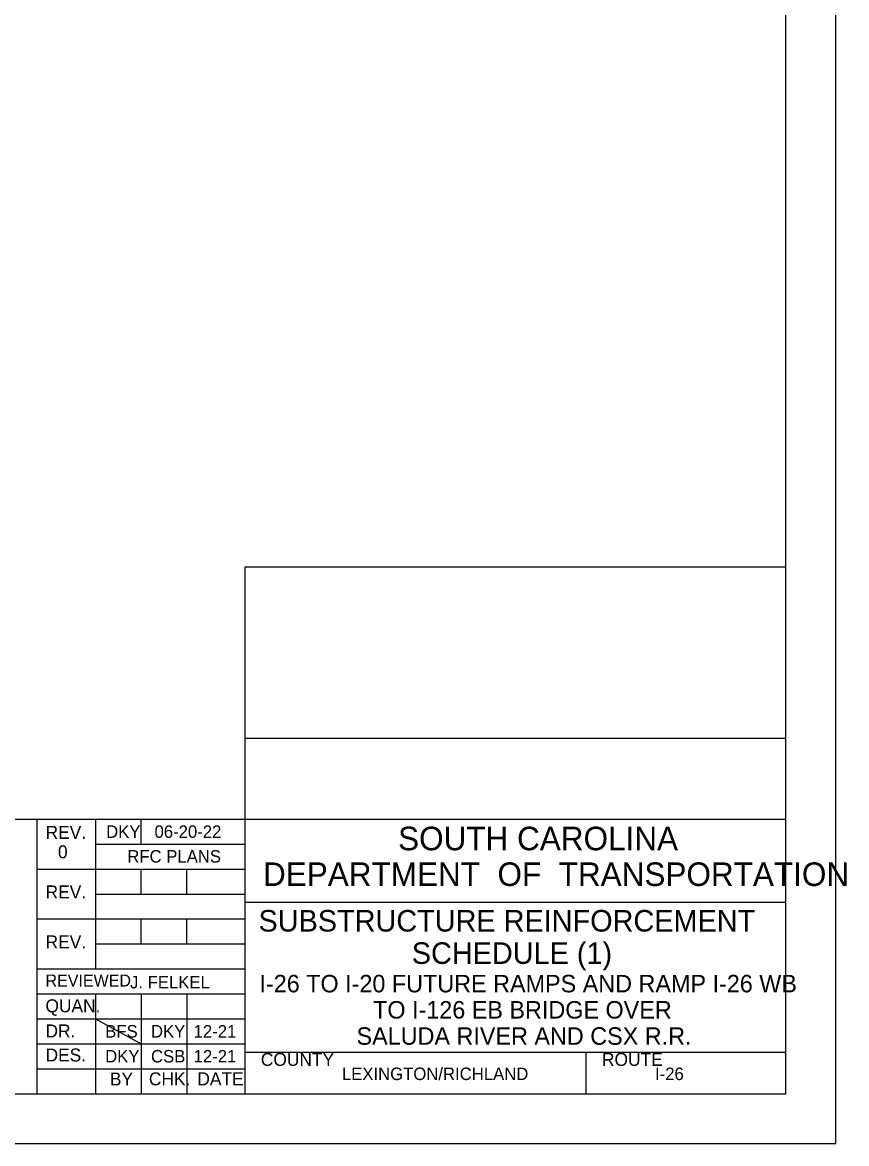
# Model space of a CAD drawing. Extents: x -121.2 to -24.9, y 6.4 to 66.3.
# Drawn here: x -46.89 to -24.88, y 6.35 to 36.3 of the extents above; entities that cross this region are included whole.
import ezdxf

# ---------------------------------------------------------------- set-up
doc = ezdxf.new("R2010")
doc.units = 0
for name, color, linetype in [('BR_BORDER LINES', 7, 'Continuous'), ('BR_TEXT', 7, 'Continuous'), ('Level 31', 7, 'Continuous')]:
    doc.layers.add(name, color=color, linetype=linetype)

msp = doc.modelspace()

# ---------------------------------------------------------------- linework, layer by layer
at = {"layer": 'BR_BORDER LINES'}
for p, q in [((-26.496, 7.683), (-26.496, 63.683)), ((-40.941, 7.683), (-40.941, 21.754)), ((-40.941, 21.754), (-26.496, 21.754)), ((-40.94, 17.182), (-26.496, 17.182)), ((-60.804, 15.017), (-46.496, 15.017)), ((-46.496, 7.683), (-46.496, 15.017)), ((-46.496, 15.017), (-26.496, 15.017)), ((-44.941, 15.017), (-44.941, 11.017)), ((-43.718, 14.35), (-43.718, 15.017)), ((-44.941, 14.35), (-40.941, 14.35)), ((-46.496, 13.684), (-40.941, 13.684)), ((-43.718, 13.017), (-43.718, 13.684)), ((-42.496, 13.017), (-42.496, 13.684)), ((-44.941, 13.017), (-40.941, 13.017)), ((-40.941, 12.795), (-40.941, 12.795)), ((-40.941, 12.795), (-26.495, 12.795)), ((-46.496, 12.35), (-40.941, 12.35)), ((-43.718, 11.684), (-43.718, 12.35)), ((-42.496, 11.684), (-42.496, 12.35)), ((-44.941, 11.684), (-40.941, 11.684)), ((-46.496, 11.017), (-40.941, 11.017)), ((-46.496, 10.35), (-40.941, 10.35)), ((-44.941, 10.35), (-44.941, 7.683)), ((-43.718, 10.35), (-43.718, 7.683)), ((-42.496, 10.35), (-42.496, 7.683)), ((-46.496, 9.683), (-40.941, 9.683)), ((-46.496, 9.017), (-40.941, 9.017)), ((-40.941, 8.795), (-26.496, 8.795)), ((-40.68, 8.795), (-26.496, 8.795)), ((-31.829, 7.683), (-31.829, 8.795)), ((-46.496, 8.35), (-40.941, 8.35)), ((-116.272, 7.683), (-26.496, 7.683))]:
    msp.add_line(p, q, dxfattribs=at)
at = {"layer": 'Level 31'}
for p, q in [((-33.717, 11.621), (-33.717, 11.621)), ((-44.941, 9.683), (-43.718, 9.017))]:
    msp.add_line(p, q, dxfattribs=at)
msp.add_lwpolyline([(-121.161, 6.35), (-25.161, 6.35), (-25.161, 65.017), (-121.161, 65.017)], close=True, dxfattribs=at)

# ---------------------------------------------------------------- texts
at = {"layer": 'BR_TEXT'}
for s, height, p in [('REV.', 0.3467, (-46.27, 14.491)), ('DKY', 0.3333, (-44.652, 14.517)), ('06-20-22', 0.3333, (-43.36, 14.517)), ('SOUTH CAROLINA', 0.62899, (-36.855, 14.186)), ('0', 0.347, (-45.94, 13.971)), ('RFC PLANS', 0.3333, (-44.087, 13.857)), ('DEPARTMENT  OF  TRANSPORTATION', 0.62899, (-40.463, 13.232)), ('REV.', 0.3467, (-46.27, 12.898)), ('SUBSTRUCTURE REINFORCEMENT', 0.576, (-40.583, 12.014)), ('REV.', 0.3467, (-46.27, 11.565)), ('SCHEDULE (1)', 0.576, (-36.489, 11.15)), ('REVIEWED', 0.32, (-46.272, 10.546)), ('J. FELKEL', 0.3333, (-44.015, 10.495)), ('I-26 TO I-20 FUTURE RAMPS AND RAMP I-26 WB', 0.46667, (-40.558, 10.39)), ('QUAN.', 0.3467, (-46.274, 9.857)), ('TO I-126 EB BRIDGE OVER', 0.46667, (-37.523, 9.69)), ('DR.', 0.3467, (-46.273, 9.186)), ('BFS', 0.3333, (-44.677, 9.183)), ('DKY', 0.3333, (-43.456, 9.183)), ('12-21', 0.3333, (-42.316, 9.183)), ('SALUDA RIVER AND CSX R.R.', 0.46667, (-37.965, 8.99)), ('DES.', 0.3467, (-46.271, 8.543)), ('DKY', 0.3333, (-44.679, 8.517)), ('CSB', 0.3333, (-43.454, 8.517)), ('12-21', 0.3333, (-42.316, 8.517)), ('COUNTY', 0.3467, (-40.521, 8.425)), ('ROUTE', 0.3467, (-31.41, 8.425)), ('LEXINGTON/RICHLAND', 0.33332, (-38.355, 8.047)), ('BY', 0.3467, (-44.553, 7.902)), ('CHK.', 0.3467, (-43.511, 7.906)), ('DATE', 0.3467, (-42.217, 7.906)), ('I-26', 0.3333, (-29.993, 8.047))]:
    msp.add_text(s, height=height, dxfattribs=at).set_placement(p)

doc.saveas('drawing.dxf')
